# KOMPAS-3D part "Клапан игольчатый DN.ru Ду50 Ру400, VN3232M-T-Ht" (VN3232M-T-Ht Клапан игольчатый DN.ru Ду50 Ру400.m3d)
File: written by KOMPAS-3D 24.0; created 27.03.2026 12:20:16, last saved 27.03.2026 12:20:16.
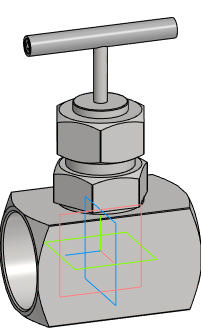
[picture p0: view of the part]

Document properties: Автор: Илья; Полное имя файла: D:\Обмен\Заказы с фриланса\DN.ru\VNxxM-T-Ht Клапан игольчатый DN.ru Ду8-50 Ру400\VN3232M-T-Ht Клапан игольчатый DN.ru Ду8-50 Ру400\DN50\VN3232M-T-Ht Клапан игольчатый DN.ru Ду50 Ру400.m3d

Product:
- Body: Body1  | qty 1
    Масса: 2.961611
- Part/product: Клапан игольчатый DN.ru Ду50 Ру400  | designation VN3232M-T-Ht
    Масса: 3
    Раздел спецификации: Прочие изделия
    Примечание: D090-02136

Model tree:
1. Body1  (labels: Body1)

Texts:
  VN3232M-T-Ht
